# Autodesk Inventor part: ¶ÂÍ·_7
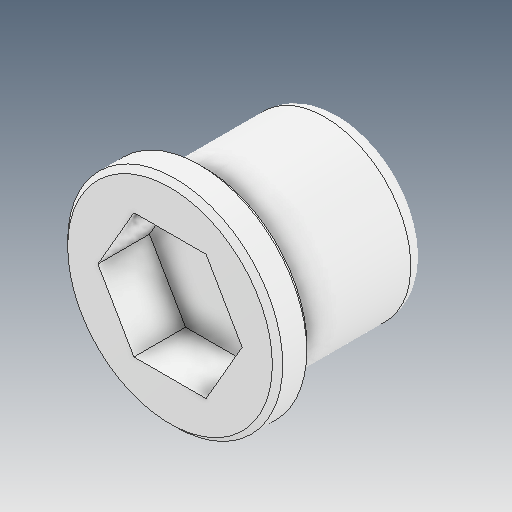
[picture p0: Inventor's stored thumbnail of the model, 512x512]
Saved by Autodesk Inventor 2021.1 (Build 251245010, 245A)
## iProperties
Created: 2021-06
Part Number: ¶ÂÍ·_7
Material: Ogólny
Document SubType Name: Modeling
Designer: user
Density: 1 g/cm^3
Appearance: Domyślna
Author: user
Revision Number: ÈÎºÎ
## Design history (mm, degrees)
feature "ÊäÈë1"
node "Bryła1"
